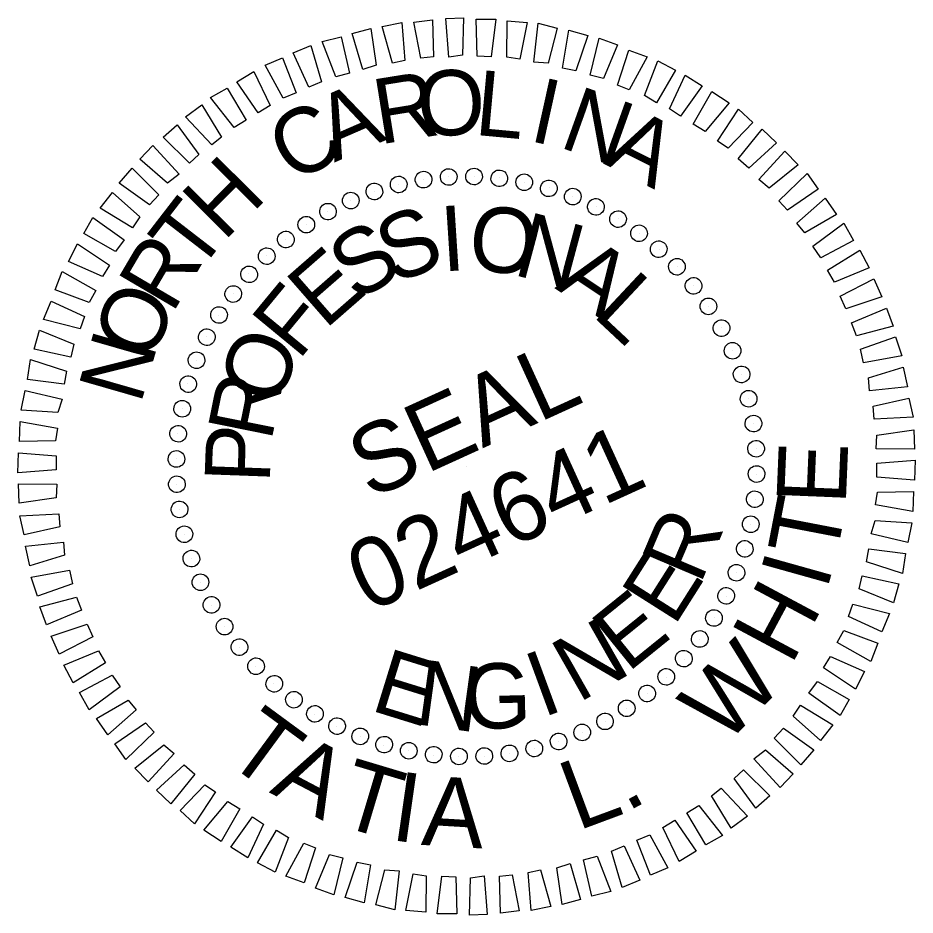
# Model space of a CAD drawing. Extents: x 2249053 to 2251039, y 663030 to 664800.
# Drawn here: x 2250811.5 to 2250889.1, y 664680.9 to 664758.5 of the extents above; entities that cross this region are included whole.
import ezdxf

# ---------------------------------------------------------------- set-up
doc = ezdxf.new("R2010")
doc.units = 0
doc.layers.add('Sheet Professional Seal CELL', color=7, linetype='Continuous')

msp = doc.modelspace()

# ---------------------------------------------------------------- linework, layer by layer
at = {"layer": 'Sheet Professional Seal CELL'}
for p, q in [((2250844.46, 664744.043), (2250844.46, 664744.043)), ((2250846.557, 664744.505), (2250846.557, 664744.505)), ((2250848.758, 664744.739), (2250848.758, 664744.739)), ((2250850.951, 664744.75), (2250850.951, 664744.75)), ((2250853.141, 664744.65), (2250853.141, 664744.65)), ((2250855.297, 664744.259), (2250855.297, 664744.259)), ((2250842.358, 664743.47), (2250842.358, 664743.47)), ((2250857.449, 664743.757), (2250857.449, 664743.757)), ((2250840.294, 664742.693), (2250840.294, 664742.693)), ((2250859.482, 664743.035), (2250859.482, 664743.035)), ((2250838.313, 664741.735), (2250838.313, 664741.735)), ((2250861.531, 664742.156), (2250861.531, 664742.156)), ((2250863.395, 664741.082), (2250863.395, 664741.082)), ((2250836.482, 664740.57), (2250836.482, 664740.57)), ((2250865.229, 664739.831), (2250865.229, 664739.831)), ((2250834.646, 664739.294), (2250834.646, 664739.294)), ((2250832.984, 664737.876), (2250832.984, 664737.876)), ((2250866.948, 664738.471), (2250866.948, 664738.471)), ((2250831.496, 664736.319), (2250831.496, 664736.319)), ((2250868.506, 664736.984), (2250868.506, 664736.984)), ((2250869.923, 664735.322), (2250869.923, 664735.322)), ((2250830.137, 664734.6), (2250830.137, 664734.6)), ((2250871.2, 664733.486), (2250871.2, 664733.486)), ((2250828.885, 664732.765), (2250828.885, 664732.765)), ((2250872.365, 664731.654), (2250872.365, 664731.654)), ((2250827.812, 664730.902), (2250827.812, 664730.902)), ((2250873.323, 664729.673), (2250873.323, 664729.673)), ((2250826.933, 664728.852), (2250826.933, 664728.852)), ((2250874.099, 664727.609), (2250874.099, 664727.609)), ((2250826.211, 664726.82), (2250826.211, 664726.82)), ((2250874.673, 664725.508), (2250874.673, 664725.508)), ((2250825.709, 664724.667), (2250825.709, 664724.667)), ((2250875.135, 664723.41), (2250875.135, 664723.41)), ((2250825.318, 664722.511), (2250825.318, 664722.511)), ((2250875.369, 664721.209), (2250875.369, 664721.209)), ((2250825.217, 664720.322), (2250825.217, 664720.322)), ((2250850.299, 664719.669), (2250850.299, 664719.669)), ((2250875.38, 664719.016), (2250875.38, 664719.016)), ((2250825.228, 664718.129), (2250825.228, 664718.129)), ((2250875.279, 664716.827), (2250875.279, 664716.827)), ((2250825.462, 664715.928), (2250825.462, 664715.928)), ((2250874.889, 664714.671), (2250874.889, 664714.671)), ((2250825.924, 664713.83), (2250825.924, 664713.83)), ((2250874.386, 664712.518), (2250874.386, 664712.518)), ((2250826.498, 664711.729), (2250826.498, 664711.729)), ((2250873.665, 664710.486), (2250873.665, 664710.486)), ((2250827.274, 664709.665), (2250827.274, 664709.665)), ((2250872.786, 664708.436), (2250872.786, 664708.436)), ((2250828.232, 664707.684), (2250828.232, 664707.684)), ((2250871.712, 664706.573), (2250871.712, 664706.573)), ((2250829.397, 664705.852), (2250829.397, 664705.852)), ((2250870.46, 664704.738), (2250870.46, 664704.738)), ((2250830.674, 664704.016), (2250830.674, 664704.016)), ((2250869.101, 664703.019), (2250869.101, 664703.019)), ((2250832.091, 664702.354), (2250832.091, 664702.354)), ((2250867.613, 664701.462), (2250867.613, 664701.462)), ((2250833.649, 664700.867), (2250833.649, 664700.867)), ((2250865.951, 664700.044), (2250865.951, 664700.044)), ((2250835.368, 664699.507), (2250835.368, 664699.507)), ((2250837.202, 664698.256), (2250837.202, 664698.256)), ((2250864.116, 664698.768), (2250864.116, 664698.768)), ((2250862.284, 664697.603), (2250862.284, 664697.603)), ((2250839.066, 664697.182), (2250839.066, 664697.182)), ((2250841.115, 664696.303), (2250841.115, 664696.303)), ((2250860.303, 664696.644), (2250860.303, 664696.644)), ((2250843.148, 664695.581), (2250843.148, 664695.581)), ((2250856.137, 664695.295), (2250856.137, 664695.295)), ((2250858.239, 664695.868), (2250858.239, 664695.868)), ((2250845.3, 664695.079), (2250845.3, 664695.079)), ((2250847.457, 664694.688), (2250847.457, 664694.688)), ((2250849.646, 664694.588), (2250849.646, 664694.588)), ((2250851.839, 664694.598), (2250851.839, 664694.598)), ((2250854.04, 664694.833), (2250854.04, 664694.833))]:
    msp.add_line(p, q, dxfattribs=at)
for points in [[(2250843.897, 664754.557), (2250843.003, 664757.722), (2250844.716, 664758.063), (2250844.956, 664754.766)], [(2250846.35, 664754.962), (2250845.746, 664758.093), (2250847.364, 664758.282), (2250847.451, 664755.079)], [(2250848.771, 664755.076), (2250848.51, 664758.42), (2250850.033, 664758.454), (2250849.962, 664755.235)], [(2250851.212, 664755.145), (2250851.126, 664758.348), (2250852.826, 664758.354), (2250852.441, 664755.101)], [(2250853.782, 664755.053), (2250853.828, 664758.207), (2250855.545, 664758.056), (2250854.895, 664754.902)], [(2250856.116, 664754.634), (2250856.505, 664757.999), (2250858.124, 664757.583), (2250857.366, 664754.544)], [(2250841.348, 664754), (2250840.43, 664757.098), (2250842.035, 664757.555), (2250842.503, 664754.361)], [(2250858.604, 664754.12), (2250859.146, 664757.389), (2250860.785, 664756.928), (2250859.759, 664753.877)], [(2250838.999, 664753.368), (2250837.832, 664756.408), (2250839.458, 664756.82), (2250840.174, 664753.684)], [(2250860.976, 664753.498), (2250861.762, 664756.714), (2250863.352, 664756.12), (2250862.151, 664753.209)], [(2250836.662, 664752.467), (2250835.314, 664755.424), (2250836.836, 664756.063), (2250837.775, 664752.92)], [(2250863.34, 664752.652), (2250864.321, 664755.682), (2250865.911, 664755.088), (2250864.354, 664752.236)], [(2250834.457, 664751.517), (2250832.882, 664754.37), (2250834.404, 664755.01), (2250835.57, 664751.969)], [(2250865.679, 664751.741), (2250866.838, 664754.742), (2250868.353, 664753.949), (2250866.73, 664751.121)], [(2250832.287, 664750.252), (2250830.458, 664752.936), (2250831.922, 664753.823), (2250833.316, 664750.887)], [(2250867.853, 664750.589), (2250869.21, 664753.516), (2250870.676, 664752.591), (2250868.793, 664749.973)], [(2250830.227, 664748.984), (2250828.172, 664751.563), (2250829.611, 664752.384), (2250831.257, 664749.618)], [(2250869.886, 664749.263), (2250871.509, 664752.091), (2250872.995, 664751.12), (2250870.938, 664748.643)], [(2250828.272, 664747.488), (2250826.01, 664749.918), (2250827.411, 664750.942), (2250829.123, 664748.151)], [(2250871.981, 664747.8), (2250873.803, 664750.554), (2250875.038, 664749.414), (2250872.922, 664747.185)], [(2250826.358, 664745.9), (2250824.067, 664748.153), (2250825.29, 664749.205), (2250827.168, 664746.654)], [(2250873.783, 664746.259), (2250875.845, 664748.848), (2250877.1, 664747.662), (2250874.695, 664745.466)], [(2250824.46, 664744.156), (2250822.074, 664746.255), (2250823.19, 664747.424), (2250825.473, 664744.948)], [(2250875.577, 664744.494), (2250877.813, 664746.942), (2250878.956, 664745.76), (2250876.468, 664743.746)], [(2250822.894, 664742.288), (2250820.277, 664744.172), (2250821.397, 664745.452), (2250823.709, 664743.154)], [(2250877.301, 664742.642), (2250879.735, 664745.016), (2250880.693, 664743.64), (2250878.055, 664741.832)], [(2250821.436, 664740.304), (2250818.633, 664741.993), (2250819.711, 664743.364), (2250822.051, 664741.244)], [(2250878.842, 664740.708), (2250881.314, 664742.879), (2250882.293, 664741.457), (2250879.551, 664739.877)], [(2250819.953, 664738.254), (2250817.212, 664739.807), (2250818, 664741.21), (2250820.705, 664739.256)], [(2250880.248, 664738.711), (2250882.914, 664740.696), (2250883.756, 664739.211), (2250880.928, 664737.702)], [(2250818.847, 664736.101), (2250815.895, 664737.393), (2250816.687, 664738.908), (2250819.441, 664737.086)], [(2250881.516, 664736.651), (2250884.307, 664738.364), (2250885.104, 664736.858), (2250882.105, 664735.601)], [(2250817.67, 664733.861), (2250814.755, 664734.95), (2250815.349, 664736.539), (2250818.244, 664734.892)], [(2250882.599, 664734.398), (2250885.494, 664735.882), (2250886.199, 664734.336), (2250883.097, 664733.306)], [(2250816.895, 664731.584), (2250813.724, 664732.391), (2250814.384, 664733.956), (2250817.291, 664732.644)], [(2250883.591, 664732.102), (2250886.589, 664733.359), (2250887.183, 664731.817), (2250883.998, 664730.969)], [(2250816.091, 664729.129), (2250812.916, 664729.825), (2250813.377, 664731.464), (2250816.354, 664730.238)], [(2250884.359, 664729.815), (2250887.395, 664730.869), (2250887.918, 664729.24), (2250884.629, 664728.619)], [(2250815.514, 664726.778), (2250812.352, 664727.205), (2250812.615, 664728.918), (2250815.711, 664727.912)], [(2250885.053, 664727.329), (2250888.04, 664728.251), (2250888.426, 664726.559), (2250885.125, 664726.207)], [(2250814.979, 664724.336), (2250811.809, 664724.539), (2250812.138, 664726.228), (2250815.334, 664725.487)], [(2250885.457, 664724.875), (2250888.548, 664725.57), (2250888.914, 664723.923), (2250885.529, 664723.754)], [(2250814.779, 664721.882), (2250811.667, 664721.837), (2250811.707, 664723.558), (2250814.931, 664722.995)], [(2250885.771, 664722.38), (2250888.965, 664722.848), (2250889.016, 664721.168), (2250885.706, 664721.197)], [(2250814.824, 664719.374), (2250811.526, 664719.134), (2250811.565, 664720.856), (2250814.822, 664720.583)], [(2250885.774, 664719.964), (2250889.071, 664720.204), (2250889.032, 664718.482), (2250885.775, 664718.755)], [(2250814.826, 664716.958), (2250811.632, 664716.49), (2250811.581, 664718.17), (2250814.891, 664718.141)], [(2250885.818, 664717.456), (2250888.93, 664717.501), (2250888.89, 664715.78), (2250885.666, 664716.343)], [(2250815.14, 664714.463), (2250812.05, 664713.768), (2250811.683, 664715.415), (2250815.068, 664715.584)], [(2250885.618, 664715.002), (2250888.788, 664714.799), (2250888.459, 664713.11), (2250885.264, 664713.851)], [(2250815.544, 664712.009), (2250812.558, 664711.087), (2250812.171, 664712.779), (2250815.472, 664713.131)], [(2250885.083, 664712.56), (2250888.245, 664712.133), (2250887.982, 664710.42), (2250884.886, 664711.426)], [(2250816.238, 664709.523), (2250813.202, 664708.469), (2250812.679, 664710.098), (2250815.968, 664710.719)], [(2250884.507, 664710.209), (2250887.681, 664709.513), (2250887.22, 664707.874), (2250884.243, 664709.1)], [(2250817.006, 664707.236), (2250814.008, 664705.978), (2250813.414, 664707.521), (2250816.6, 664708.369)], [(2250883.703, 664707.754), (2250886.873, 664706.947), (2250886.213, 664705.382), (2250883.307, 664706.694)], [(2250817.998, 664704.94), (2250815.103, 664703.456), (2250814.398, 664705.002), (2250817.5, 664706.032)], [(2250882.927, 664705.477), (2250885.842, 664704.388), (2250885.248, 664702.799), (2250882.353, 664704.446)], [(2250819.081, 664702.687), (2250816.29, 664700.974), (2250815.493, 664702.479), (2250818.492, 664703.737)], [(2250881.751, 664703.237), (2250884.703, 664701.945), (2250883.91, 664700.43), (2250881.156, 664702.252)], [(2250820.35, 664700.627), (2250817.683, 664698.642), (2250816.841, 664700.127), (2250819.67, 664701.636)], [(2250880.644, 664701.084), (2250883.385, 664699.531), (2250882.597, 664698.128), (2250879.892, 664700.082)], [(2250821.755, 664698.63), (2250819.283, 664696.459), (2250818.304, 664697.881), (2250821.046, 664699.461)], [(2250879.161, 664699.034), (2250881.965, 664697.345), (2250880.886, 664695.974), (2250878.546, 664698.094)], [(2250823.296, 664696.696), (2250820.862, 664694.322), (2250819.904, 664695.698), (2250822.542, 664697.506)], [(2250877.703, 664697.05), (2250880.32, 664695.166), (2250879.2, 664693.886), (2250876.889, 664696.184)], [(2250825.02, 664694.844), (2250822.784, 664692.396), (2250821.641, 664693.578), (2250824.129, 664695.592)], [(2250876.137, 664695.182), (2250878.523, 664693.083), (2250877.407, 664691.914), (2250875.124, 664694.39)], [(2250826.814, 664693.079), (2250824.752, 664690.49), (2250823.497, 664691.676), (2250825.903, 664693.872)], [(2250874.239, 664693.438), (2250876.53, 664691.185), (2250875.307, 664690.133), (2250873.429, 664692.683)], [(2250828.616, 664691.538), (2250826.794, 664688.784), (2250825.56, 664689.924), (2250827.676, 664692.153)], [(2250872.325, 664691.85), (2250874.588, 664689.42), (2250873.186, 664688.396), (2250871.474, 664691.187)], [(2250830.711, 664690.075), (2250829.088, 664687.247), (2250827.602, 664688.218), (2250829.66, 664690.695)], [(2250870.37, 664690.354), (2250872.425, 664687.775), (2250870.986, 664686.954), (2250869.34, 664689.72)], [(2250832.745, 664688.749), (2250831.387, 664685.822), (2250829.921, 664686.747), (2250831.805, 664689.365)], [(2250868.311, 664689.086), (2250870.139, 664686.402), (2250868.675, 664685.515), (2250867.281, 664688.451)], [(2250834.919, 664687.597), (2250833.759, 664684.596), (2250832.244, 664685.389), (2250833.867, 664688.217)], [(2250866.14, 664687.821), (2250867.716, 664684.968), (2250866.194, 664684.328), (2250865.027, 664687.369)], [(2250837.258, 664686.686), (2250836.276, 664683.656), (2250834.687, 664684.25), (2250836.243, 664687.102)], [(2250863.935, 664686.871), (2250865.284, 664683.914), (2250863.762, 664683.274), (2250862.823, 664686.418)], [(2250839.621, 664685.84), (2250838.835, 664682.624), (2250837.245, 664683.218), (2250838.446, 664686.129)], [(2250861.598, 664685.97), (2250862.765, 664682.93), (2250861.139, 664682.518), (2250860.424, 664685.654)], [(2250841.993, 664685.218), (2250841.451, 664681.949), (2250839.812, 664682.41), (2250840.838, 664685.461)], [(2250859.249, 664685.338), (2250860.167, 664682.24), (2250858.562, 664681.783), (2250858.095, 664684.977)], [(2250844.481, 664684.704), (2250844.092, 664681.339), (2250842.473, 664681.755), (2250843.231, 664684.794)], [(2250846.815, 664684.285), (2250846.769, 664681.131), (2250845.052, 664681.282), (2250845.702, 664684.436)], [(2250854.247, 664684.376), (2250854.851, 664681.245), (2250853.233, 664681.056), (2250853.146, 664684.259)], [(2250856.7, 664684.781), (2250857.594, 664681.616), (2250855.881, 664681.275), (2250855.641, 664684.572)], [(2250849.385, 664684.193), (2250849.472, 664680.99), (2250847.771, 664680.984), (2250848.156, 664684.237)], [(2250851.826, 664684.262), (2250852.087, 664680.918), (2250850.564, 664680.884), (2250850.635, 664684.103)]]:
    msp.add_lwpolyline(points, close=True, dxfattribs=at)
for centre, major_axis in [((2250844.439, 664744.055), (-0.168, 0.7)), ((2250846.586, 664744.473), (-0.107, 0.712)), ((2250848.762, 664744.702), (-0.044, 0.719)), ((2250850.95, 664744.741), (0.019, 0.72)), ((2250853.132, 664744.588), (0.081, 0.715)), ((2250855.293, 664744.247), (0.143, 0.706)), ((2250842.336, 664743.451), (-0.229, 0.683)), ((2250857.417, 664743.718), (0.204, 0.69)), ((2250840.293, 664742.667), (-0.287, 0.66)), ((2250859.485, 664743.006), (0.264, 0.67)), ((2250838.327, 664741.707), (-0.344, 0.633)), ((2250861.484, 664742.116), (0.321, 0.644)), ((2250863.398, 664741.056), (0.376, 0.614)), ((2250836.452, 664740.58), (-0.398, 0.6)), ((2250865.212, 664739.833), (0.428, 0.579)), ((2250834.682, 664739.293), (-0.448, 0.563)), ((2250833.031, 664737.858), (-0.496, 0.522)), ((2250866.913, 664738.456), (0.477, 0.539)), ((2250831.511, 664736.283), (-0.539, 0.477)), ((2250868.487, 664736.937), (0.522, 0.496)), ((2250869.923, 664735.286), (0.563, 0.448)), ((2250830.135, 664734.583), (-0.579, 0.428)), ((2250871.209, 664733.516), (0.6, 0.398)), ((2250828.912, 664732.769), (-0.614, 0.376)), ((2250872.337, 664731.641), (0.633, 0.344)), ((2250827.851, 664730.855), (-0.644, 0.321)), ((2250873.296, 664729.675), (0.66, 0.287)), ((2250826.962, 664728.856), (-0.67, 0.264)), ((2250874.081, 664727.632), (0.683, 0.229)), ((2250826.25, 664726.787), (-0.69, 0.204)), ((2250874.684, 664725.529), (0.7, 0.168)), ((2250825.721, 664724.664), (-0.706, 0.143)), ((2250875.102, 664723.381), (0.712, 0.107)), ((2250825.379, 664722.503), (-0.715, 0.081)), ((2250875.331, 664721.205), (0.719, 0.044)), ((2250825.227, 664720.32), (-0.72, 0.019)), ((2250875.37, 664719.018), (0.72, -0.019)), ((2250825.266, 664718.133), (-0.719, -0.044)), ((2250875.218, 664716.835), (0.715, -0.081)), ((2250825.495, 664715.957), (-0.712, -0.107)), ((2250874.876, 664714.674), (0.706, -0.143)), ((2250825.913, 664713.809), (-0.7, -0.168)), ((2250874.347, 664712.551), (0.69, -0.204)), ((2250826.516, 664711.706), (-0.683, -0.229)), ((2250873.635, 664710.482), (0.67, -0.264)), ((2250827.301, 664709.663), (-0.66, -0.287)), ((2250872.746, 664708.483), (0.644, -0.321)), ((2250828.26, 664707.697), (-0.633, -0.344)), ((2250871.686, 664706.569), (0.614, -0.376)), ((2250829.388, 664705.822), (-0.6, -0.398)), ((2250870.463, 664704.755), (0.579, -0.428)), ((2250830.674, 664704.052), (-0.563, -0.448)), ((2250869.086, 664703.055), (0.539, -0.477)), ((2250832.11, 664702.401), (-0.522, -0.496)), ((2250867.566, 664701.48), (0.496, -0.522)), ((2250833.684, 664700.882), (-0.477, -0.539)), ((2250865.915, 664700.045), (0.448, -0.563)), ((2250835.385, 664699.505), (-0.428, -0.579)), ((2250837.199, 664698.282), (-0.376, -0.614)), ((2250864.146, 664698.758), (0.398, -0.6)), ((2250862.27, 664697.631), (0.344, -0.633)), ((2250839.113, 664697.222), (-0.321, -0.644)), ((2250860.304, 664696.671), (0.287, -0.66)), ((2250841.112, 664696.332), (-0.264, -0.67)), ((2250843.181, 664695.62), (-0.204, -0.69)), ((2250856.159, 664695.283), (0.168, -0.7)), ((2250858.262, 664695.887), (0.229, -0.683)), ((2250845.304, 664695.091), (-0.143, -0.706)), ((2250847.465, 664694.75), (-0.081, -0.715)), ((2250849.647, 664694.597), (-0.019, -0.72)), ((2250851.835, 664694.636), (0.044, -0.719)), ((2250854.011, 664694.865), (0.107, -0.712))]:
    msp.add_ellipse(centre, major_axis=major_axis, ratio=0.999708, dxfattribs=at)

# ---------------------------------------------------------------- texts
for s, height, rotation, p in [('R', 5.638, 9.13336, (2250842.771, 664747.505)), ('O', 5.638, 1.93343, (2250846.131, 664748.212)), ('L', 5.638, 354.73314, (2250850.902, 664748.355)), ('I', 5.638, 347.5324, (2250855.582, 664747.851)), ('A', 5.638, 23.53258, (2250838.867, 664745.944)), ('N', 5.639, 340.33117, (2250858.182, 664747.333)), ('C', 5.638, 30.73213, (2250835.397, 664744.033)), ('A', 5.639, 333.12941, (2250862.09, 664745.873)), ('H', 5.638, 45.13174, (2250829.312, 664739.06)), ('T', 5.638, 52.33203, (2250827.04, 664736.21)), ('S', 5.638, 22.41266, (2250844.015, 664735.378)), ('I', 5.638, 3.70186, (2250848.218, 664736.525)), ('O', 5.638, 354.34574, (2250850.328, 664736.718)), ('N', 5.638, 344.98887, (2250854.206, 664736.288)), ('S', 5.638, 31.76787, (2250840.76, 664733.839)), ('R', 5.638, 59.53277, (2250824.859, 664732.798)), ('E', 5.638, 41.12333, (2250838.057, 664731.452)), ('A', 5.639, 326.27253, (2250857.878, 664735.105)), ('L', 5.639, 316.91311, (2250861.083, 664732.775)), ('F', 5.638, 50.47929, (2250835.767, 664728.759)), ('O', 5.638, 66.734, (2250823.006, 664728.546)), ('N', 5.639, 73.93576, (2250822.116, 664724.953)), ('O', 5.639, 69.1935, (2250833.989, 664724.706)), ('SEAL', 5.9982, 24.51226, (2250841.941, 664716.791)), ('R', 5.639, 78.55191, (2250833.413, 664721.751)), ('P', 5.639, 87.91115, (2250833.285, 664718.176)), ('024641', 5.9982, 24.51226, (2250841.819, 664707.001)), ('E', 5.998, 87.63115, (2250883.078, 664716.311)), ('T', 5.998, 79.10933, (2250882.219, 664711.491)), ('R', 5.639, 66.99367, (2250870.492, 664709.369)), ('E', 5.638, 57.63635, (2250868.237, 664705.758)), ('I', 5.998, 74.34486, (2250881.429, 664708.868)), ('H', 5.998, 61.83328, (2250878.35, 664702.38)), ('E', 5.638, 38.92402, (2250864.224, 664701.784)), ('N', 5.638, 29.56865, (2250859.969, 664699.185)), ('W', 5.998, 46.12601, (2250872.622, 664695.432)), ('E', 5.638, 342.78915, (2250841.87, 664698.625)), ('I', 5.638, 20.21346, (2250856.858, 664697.931)), ('N', 5.638, 352.14622, (2250845.72, 664697.413)), ('G', 5.638, 1.5025, (2250850.111, 664696.943)), ('T', 5.998, 323.6774, (2250829.205, 664694.354)), ('A', 5.998, 332.19922, (2250833.189, 664691.508)), ('T', 5.998, 343.27759, (2250838.92, 664688.745)), ('L', 5.998, 20.42498, (2250859.903, 664688.148)), ('I', 5.998, 351.79941, (2250843.628, 664687.4)), ('A', 5.998, 356.56388, (2250846.331, 664686.957)), ('.', 5.998, 28.28829, (2250864.125, 664689.759))]:
    msp.add_text(s, height=height, rotation=rotation, dxfattribs=at).set_placement(p)

doc.saveas('drawing.dxf')
